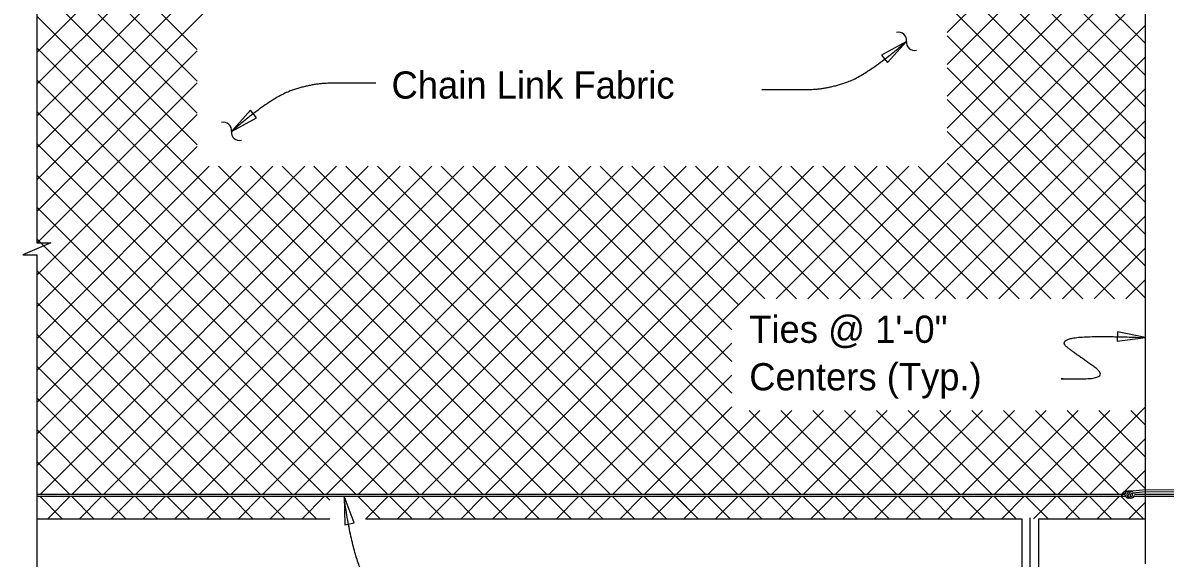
# Model space of a CAD drawing. Extents: x 0 to 72.1, y -15.2 to 30.1.
# Drawn here: x 16.16 to 24.63, y 18.99 to 22.95 of the extents above; entities that cross this region are included whole.
import ezdxf

# ---------------------------------------------------------------- set-up
doc = ezdxf.new("R2010")
doc.units = 0
for name, color, linetype in [('AdhocPoint_dp', 7, 'Continuous'), ('Border', 7, 'Continuous'), ('Patterning', 7, 'Continuous'), ('PlotBorder_dp', 7, 'Continuous'), ('SheetBorder_dp', 7, 'Continuous'), ('SheetLines_dp', 7, 'Continuous'), ('TextMisc', 7, 'Continuous')]:
    doc.layers.add(name, color=color, linetype=linetype)

msp = doc.modelspace()

# ---------------------------------------------------------------- linework, layer by layer
at = {"layer": 'AdhocPoint_dp'}
for p, q in [((16.268, 19.2783), (18.44, 19.2783)), ((18.704, 19.2783), (23.5698, 19.2783)), ((23.5698, 19.2783), (23.5698, 14.757)), ((23.6923, 19.2783), (23.6923, 15.6116)), ((23.6923, 19.2783), (24.4852, 19.2783))]:
    msp.add_line(p, q, dxfattribs=at)
at = {"layer": 'Border'}
for p, q in [((24.4852, 19.4597), (24.7769, 19.4597)), ((24.4852, 19.445), (24.7769, 19.445))]:
    msp.add_line(p, q, dxfattribs=at)
at = {"layer": 'Patterning'}
for p, q in [((16.268, 21.7902), (19.5747, 25.0969)), ((16.268, 22.2616), (19.1033, 25.0969)), ((16.268, 22.733), (18.6318, 25.0969)), ((16.268, 22.0259), (19.339, 25.0969)), ((16.268, 22.4973), (18.8675, 25.0969)), ((21.0086, 25.0969), (24.4852, 21.6202)), ((21.2443, 25.0969), (24.4852, 21.8559)), ((21.48, 25.0969), (24.4852, 22.0916)), ((21.7157, 25.0969), (24.4852, 22.3273)), ((21.9514, 25.0969), (24.4852, 22.563)), ((22.1871, 25.0969), (24.4852, 22.7987)), ((23.0145, 22.8799), (24.4852, 24.3506)), ((23.0145, 22.6442), (24.4852, 24.1149)), ((16.268, 23.9449), (17.4577, 22.7552)), ((23.0145, 22.4085), (24.4852, 23.8792)), ((16.268, 23.7092), (17.4577, 22.5195)), ((23.0145, 22.1728), (24.4852, 23.6435)), ((16.268, 23.4735), (17.4577, 22.2838)), ((21.9837, 20.9063), (24.4852, 23.4078)), ((16.2393, 23.2665), (17.4577, 22.0481)), ((22.2194, 20.9063), (24.4852, 23.1721)), ((16.268, 23.0021), (19.8104, 19.4597)), ((22.4551, 20.9063), (24.4852, 22.9364)), ((23.0145, 22.8552), (24.4852, 21.3845)), ((16.268, 22.7664), (19.5747, 19.4597)), ((16.268, 21.5545), (17.4577, 22.7442)), ((22.6908, 20.9063), (24.4852, 22.7007)), ((23.0145, 22.6195), (24.4852, 21.1488)), ((16.268, 22.5307), (19.339, 19.4597)), ((16.2718, 21.3227), (17.4577, 22.5085)), ((22.9265, 20.9063), (24.4852, 22.465)), ((23.0145, 22.3838), (24.4852, 20.9131)), ((16.268, 22.295), (19.1033, 19.4597)), ((16.268, 21.0831), (17.4577, 22.2728)), ((23.1623, 20.9063), (24.4852, 22.2293)), ((23.0145, 22.1481), (24.2563, 20.9063)), ((16.268, 22.0593), (18.8675, 19.4597)), ((16.268, 20.8474), (17.4577, 22.0371)), ((23.398, 20.9063), (24.4852, 21.9936)), ((16.268, 19.9046), (18.2538, 21.8904)), ((16.268, 20.376), (17.7824, 21.8904)), ((16.268, 20.6117), (17.5467, 21.8904)), ((16.268, 20.1403), (18.0181, 21.8904)), ((16.268, 19.6689), (18.4895, 21.8904)), ((16.2945, 19.4597), (18.7252, 21.8904)), ((16.5302, 19.4597), (18.9609, 21.8904)), ((16.7659, 19.4597), (19.1966, 21.8904)), ((17.0016, 19.4597), (19.4323, 21.8904)), ((17.2373, 19.4597), (19.668, 21.8904)), ((17.473, 19.4597), (19.9037, 21.8904)), ((17.6154, 21.8904), (20.0461, 19.4597)), ((17.7087, 19.4597), (20.1394, 21.8904)), ((17.8511, 21.8904), (20.2818, 19.4597)), ((17.9444, 19.4597), (20.3751, 21.8904)), ((18.0868, 21.8904), (20.5175, 19.4597)), ((18.1801, 19.4597), (20.6108, 21.8904)), ((18.3225, 21.8904), (20.7532, 19.4597)), ((18.4158, 19.4597), (20.8465, 21.8904)), ((18.5582, 21.8904), (21.1067, 19.3419)), ((18.6515, 19.4597), (21.0822, 21.8904)), ((18.7939, 21.8904), (21.2246, 19.4597)), ((18.8872, 19.4597), (21.3179, 21.8904)), ((19.0296, 21.8904), (21.4603, 19.4597)), ((19.1229, 19.4597), (21.5536, 21.8904)), ((19.2653, 21.8904), (21.696, 19.4597)), ((19.3586, 19.4597), (21.7893, 21.8904)), ((19.501, 21.8904), (21.9317, 19.4597)), ((19.5943, 19.4597), (22.025, 21.8904)), ((19.7122, 19.3419), (22.2607, 21.8904)), ((19.7367, 21.8904), (21.42, 20.2072)), ((19.9724, 21.8904), (21.42, 20.4429)), ((20.0657, 19.4597), (22.4964, 21.8904)), ((20.2081, 21.8904), (21.42, 20.6786)), ((20.4438, 21.8904), (21.4701, 20.8641)), ((20.6795, 21.8904), (21.6636, 20.9063)), ((20.9152, 21.8904), (21.8993, 20.9063)), ((21.1509, 21.8904), (22.135, 20.9063)), ((21.3866, 21.8904), (22.3707, 20.9063)), ((21.6223, 21.8904), (22.6064, 20.9063)), ((21.748, 20.9063), (22.7321, 21.8904)), ((21.858, 21.8904), (22.8421, 20.9063)), ((22.0937, 21.8904), (23.0778, 20.9063)), ((22.3294, 21.8904), (23.3135, 20.9063)), ((22.5651, 21.8904), (23.5492, 20.9063)), ((22.8008, 21.8904), (23.7849, 20.9063)), ((23.0145, 21.9124), (24.0206, 20.9063)), ((16.268, 21.8236), (18.6318, 19.4597)), ((23.6337, 20.9063), (24.4852, 21.7579)), ((16.268, 21.5879), (18.3961, 19.4597)), ((23.8694, 20.9063), (24.4852, 21.5222)), ((16.268, 21.3522), (18.1604, 19.4597)), ((24.1051, 20.9063), (24.4852, 21.2865)), ((16.268, 21.1165), (17.9247, 19.4597)), ((24.3408, 20.9063), (24.4852, 21.0508)), ((16.268, 20.8808), (17.689, 19.4597)), ((16.268, 20.6451), (17.4533, 19.4597)), ((20.3015, 19.4597), (21.42, 20.5782)), ((16.268, 20.4094), (17.2176, 19.4597)), ((20.5372, 19.4597), (21.42, 20.3425)), ((16.268, 20.1737), (16.9819, 19.4597)), ((20.7729, 19.4597), (21.42, 20.1068)), ((21.0086, 19.4597), (21.6282, 20.0793)), ((21.2443, 19.4597), (21.8639, 20.0793)), ((21.48, 19.4597), (22.0996, 20.0793)), ((21.5478, 20.0793), (22.1674, 19.4597)), ((21.7157, 19.4597), (22.3353, 20.0793)), ((21.7835, 20.0793), (22.4031, 19.4597)), ((21.9514, 19.4597), (22.571, 20.0793)), ((22.0192, 20.0793), (22.6388, 19.4597)), ((22.1871, 19.4597), (22.8067, 20.0793)), ((22.2549, 20.0793), (22.8745, 19.4597)), ((22.4228, 19.4597), (23.0424, 20.0793)), ((22.4906, 20.0793), (23.1102, 19.4597)), ((22.6585, 19.4597), (23.2781, 20.0793)), ((22.7263, 20.0793), (23.3459, 19.4597)), ((22.8942, 19.4597), (23.5138, 20.0793)), ((22.962, 20.0793), (23.5816, 19.4597)), ((23.1299, 19.4597), (23.7495, 20.0793)), ((23.1977, 20.0793), (23.8173, 19.4597)), ((23.3656, 19.4597), (23.9852, 20.0793)), ((23.4334, 20.0793), (24.053, 19.4597)), ((23.6013, 19.4597), (24.2209, 20.0793)), ((23.6691, 20.0793), (24.2887, 19.4597)), ((23.837, 19.4597), (24.4852, 20.108)), ((23.9048, 20.0793), (24.4852, 19.4989)), ((24.1405, 20.0793), (24.4852, 19.7346)), ((24.3762, 20.0793), (24.4852, 19.9703)), ((16.268, 19.938), (16.7462, 19.4597)), ((24.0727, 19.4597), (24.4852, 19.8723)), ((16.268, 19.7023), (16.5105, 19.4597)), ((24.3243, 19.4757), (24.4852, 19.6366)), ((16.2896, 19.445), (16.4562, 19.2783)), ((16.3488, 19.2783), (16.5155, 19.445)), ((16.5253, 19.445), (16.6919, 19.2783)), ((16.5845, 19.2783), (16.7512, 19.445)), ((16.761, 19.445), (16.9276, 19.2783)), ((16.8202, 19.2783), (16.9869, 19.445)), ((16.9967, 19.445), (17.1633, 19.2783)), ((17.0559, 19.2783), (17.2226, 19.445)), ((17.2324, 19.445), (17.3991, 19.2783)), ((17.2916, 19.2783), (17.4583, 19.445)), ((17.4681, 19.445), (17.6348, 19.2783)), ((17.5273, 19.2783), (17.694, 19.445)), ((17.7038, 19.445), (17.8705, 19.2783)), ((17.763, 19.2783), (17.9297, 19.445)), ((17.9395, 19.445), (18.1062, 19.2783)), ((17.9987, 19.2783), (18.1654, 19.445)), ((18.1752, 19.445), (18.3419, 19.2783)), ((18.2344, 19.2783), (18.4011, 19.445)), ((18.4109, 19.445), (18.44, 19.4159)), ((18.6466, 19.445), (18.8133, 19.2783)), ((18.7058, 19.2783), (18.8725, 19.445)), ((18.8823, 19.445), (19.049, 19.2783)), ((18.9415, 19.2783), (19.1082, 19.445)), ((19.118, 19.445), (19.2847, 19.2783)), ((19.1772, 19.2783), (19.3439, 19.445)), ((19.3537, 19.445), (19.5204, 19.2783)), ((19.4129, 19.2783), (19.5796, 19.445)), ((19.5894, 19.445), (19.7561, 19.2783)), ((19.6486, 19.2783), (19.8153, 19.445)), ((19.8251, 19.445), (19.9918, 19.2783)), ((19.8843, 19.2783), (20.051, 19.445)), ((20.0608, 19.445), (20.2275, 19.2783)), ((20.12, 19.2783), (20.2867, 19.445)), ((20.2965, 19.445), (20.4632, 19.2783)), ((20.3557, 19.2783), (20.5224, 19.445)), ((20.5322, 19.445), (20.6989, 19.2783)), ((20.5914, 19.2783), (20.7581, 19.445)), ((20.7679, 19.445), (20.9346, 19.2783)), ((20.8271, 19.2783), (20.9938, 19.445)), ((21.0036, 19.445), (21.1703, 19.2783)), ((21.0628, 19.2783), (21.2295, 19.445)), ((21.2393, 19.445), (21.406, 19.2783)), ((21.2985, 19.2783), (21.4652, 19.445)), ((21.475, 19.445), (21.6417, 19.2783)), ((21.5342, 19.2783), (21.7009, 19.445)), ((21.7107, 19.445), (21.8774, 19.2783)), ((21.7699, 19.2783), (21.9366, 19.445)), ((21.9464, 19.445), (22.1131, 19.2783)), ((22.0057, 19.2783), (22.1723, 19.445)), ((22.1821, 19.445), (22.3488, 19.2783)), ((22.2414, 19.2783), (22.408, 19.445)), ((22.4178, 19.445), (22.5845, 19.2783)), ((22.4771, 19.2783), (22.6437, 19.445)), ((22.6535, 19.445), (22.8202, 19.2783)), ((22.7128, 19.2783), (22.8794, 19.445)), ((22.8892, 19.445), (23.0559, 19.2783)), ((22.9485, 19.2783), (23.1151, 19.445)), ((23.1249, 19.445), (23.2916, 19.2783)), ((23.1842, 19.2783), (23.3508, 19.445)), ((23.3606, 19.445), (23.5273, 19.2783)), ((23.4199, 19.2783), (23.5865, 19.445)), ((23.5963, 19.445), (23.763, 19.2783)), ((23.6556, 19.2783), (23.8222, 19.445)), ((23.832, 19.445), (23.9987, 19.2783)), ((23.8913, 19.2783), (24.0579, 19.445)), ((24.0677, 19.445), (24.2344, 19.2783)), ((24.127, 19.2783), (24.2936, 19.445)), ((24.3035, 19.445), (24.4701, 19.2783)), ((24.3084, 19.4597), (24.312, 19.4633)), ((24.3627, 19.2783), (24.4852, 19.4009))]:
    msp.add_line(p, q, dxfattribs=at)
at = {"layer": 'PlotBorder_dp'}
for points in [[(16.268, 25.2804), (16.268, 23.3241), (16.3714, 23.3241), (16.268, 23.2791), (16.1647, 23.2341), (16.268, 23.2341), (16.268, 22.3405)], [(16.268, 22.3405), (16.268, 21.3227), (16.3714, 21.3227), (16.268, 21.2777), (16.1647, 21.2327), (16.268, 21.2327), (16.268, 19.0284)], [(16.268, 19.2784), (16.268, 17.4276), (16.3714, 17.4276), (16.268, 17.3826), (16.1647, 17.3376), (16.268, 17.3376), (16.268, 14.9877)]]:
    msp.add_lwpolyline(points, dxfattribs=at)
for points in [[(22.7151, 22.8151), (22.5295, 22.7141), (22.5731, 22.6586)], [(17.711, 22.1484), (17.8965, 22.2494), (17.8529, 22.3049)], [(24.4853, 20.6199), (24.2786, 20.6637), (24.2757, 20.5932)], [(18.5457, 19.445), (18.5507, 19.2338), (18.6199, 19.2473)]]:
    msp.add_lwpolyline(points, close=True, dxfattribs=at)
for centre, start, end in [((22.6555, 22.8235), 352.34263, 104.06985), ((22.7736, 22.8076), 172.34263, 284.06985), ((17.6524, 22.1558), 352.34263, 104.06985), ((17.7706, 22.1399), 172.34263, 284.06985)]:
    msp.add_arc(centre, 0.0596, start, end, dxfattribs=at)
for points in [[(21.6418, 22.4586), (21.8439, 22.4586), (22.1175, 22.4586), (22.4243, 22.5665), (22.7145, 22.8155)], [(18.7799, 22.5048), (18.5821, 22.5048), (18.3085, 22.5048), (18.0018, 22.3969), (17.7116, 22.148)], [(23.8747, 20.3153), (23.8093, 20.3153), (24.2294, 20.3153), (23.9791, 20.4924), (23.842, 20.5951), (24.0525, 20.6376), (24.4853, 20.6199)], [(19.2088, 18.651), (18.8109, 18.651), (18.6069, 18.988), (18.5457, 19.4449)]]:
    msp.add_open_spline(points, degree=2, dxfattribs=at)
at = {"layer": 'SheetBorder_dp'}
msp.add_line((23.6311, 13.3896), (23.6311, 19.2851), dxfattribs=at)
at = {"layer": 'TextMisc'}
for p, q in [((24.4852, 18.9432), (24.4852, 25.3183)), ((24.4852, 19.4923), (24.3904, 19.4812)), ((24.4852, 19.4778), (24.3926, 19.4683)), ((24.4852, 19.4923), (24.7764, 19.494)), ((24.4852, 19.4778), (24.7764, 19.4795)), ((16.268, 19.4597), (24.3101, 19.4597)), ((16.268, 19.445), (24.3367, 19.445)), ((24.32, 19.4597), (24.3332, 19.4597)), ((24.4016, 19.445), (24.4852, 19.445)), ((24.4031, 19.4597), (24.4852, 19.4597))]:
    msp.add_line(p, q, dxfattribs=at)
for centre, major_axis, ratio, start_param, end_param in [((24.3443, 19.4455), (0.0373, 0), 0.957868, 1.486836, 3.108042), ((24.3568, 19.4599), (0.023, 0), 0.957868, 1.29026, 2.970541), ((24.3756, 19.4546), (0.0295, 0), 0.957868, 1.220941, 4.039556), ((24.389, 19.4563), (-0.0303, -0.0108), 0.724765, 4.35367, 6.324556), ((24.3654, 19.4058), (-0.0724, 0), 0.957868, 5.162149, 5.652106), ((24.358, 19.4574), (-0.0249, 0), 0.957868, 6.009018, 7.089857), ((24.3593, 19.4534), (0.0231, 0), 0.957868, 3.779554, 4.879821), ((24.3654, 19.4477), (0.0206, -0.0021), 0.798607, 4.32653, 5.220153), ((24.3789, 19.4477), (0.0206, -0.0021), 0.798607, 3.333154, 5.220153), ((24.3857, 19.4523), (-0.0139, 0), 0.957868, 5.22362, 6.905413), ((24.3801, 19.4499), (-0.00795, 0), 0.957868, 6.140374, 9.314262), ((24.3941, 19.4434), (-0.0259, 0), 0.957868, 4.777514, 5.62749), ((24.3784, 19.4557), (0.0119, 0), 0.957868, 5.725876, 7.416677), ((24.3715, 19.4665), (0.0391, 0), 0.957868, 5.082588, 5.41974), ((24.3784, 19.4557), (0.0119, 0), 0.957868, 5.639684, 5.723117), ((24.3786, 19.4544), (0.0251, 0), 0.957868, 5.531357, 6.227833), ((24.3786, 19.4544), (0.0251, 0), 0.957868, 0.407687, 0.609214)]:
    msp.add_ellipse(centre, major_axis=major_axis, ratio=ratio, start_param=start_param, end_param=end_param, dxfattribs=at)

# ---------------------------------------------------------------- texts
at = {"layer": 'PlotBorder_dp'}
for s, p in [('Ties @ 1\'-0" ', (21.5486, 20.5813)), ('Centers (Typ.)', (21.5486, 20.2293))]:
    msp.add_text(s, height=0.2016, dxfattribs=at).set_placement(p)
at = {"layer": 'SheetLines_dp'}
msp.add_text('Chain Link Fabric', height=0.2016, dxfattribs=at).set_placement((18.8971, 22.3912))

doc.saveas('drawing.dxf')
